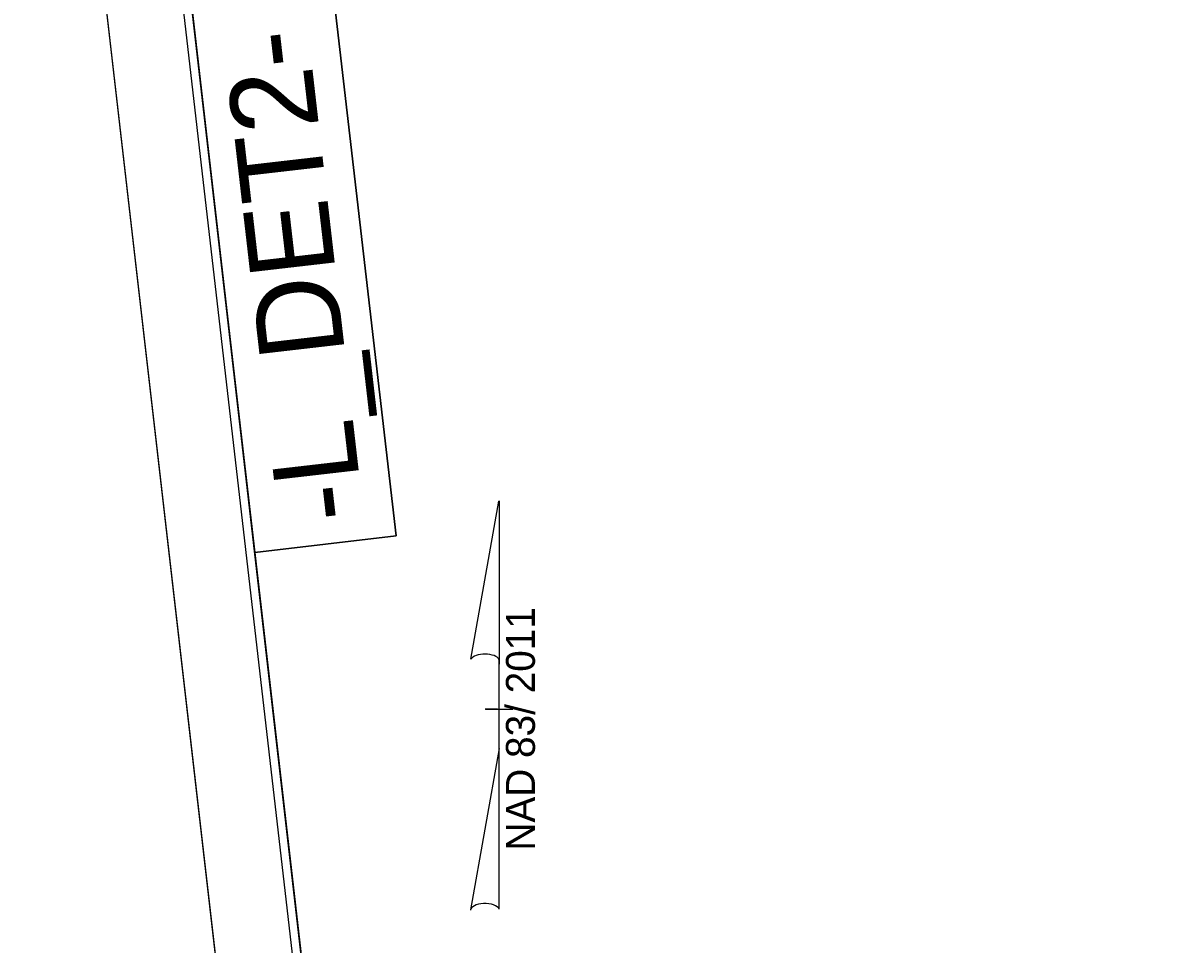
# Model space of a CAD drawing. Extents: x 477607 to 479438, y 495543 to 499482.
# Drawn here: x 477606.8 to 477940.1, y 496923.6 to 497193.8 of the extents above; entities that cross this region are included whole.
import ezdxf

# ---------------------------------------------------------------- set-up
doc = ezdxf.new("R2010")
doc.units = 0
for name, color, linetype in [('Old_Level_1', 7, 'Continuous'), ('Prop Grid Mask', 7, 'Continuous'), ('Prop North Arrow NAD83 for Plan Sheets CELL', 7, 'Continuous'), ('Sheet Border Standard 30in CELL', 7, 'Continuous'), ('Sheet Cutting Line CELL', 7, 'Continuous'), ('Sheet Layout Plan Border', 7, 'Continuous'), ('Sheet North Arrow Point CELL', 7, 'Continuous'), ('Sheet Plan CELL', 7, 'Continuous'), ('Sheet Plot Border Inside CELL', 7, 'Continuous'), ('Sheet Plot Border Outside CELL', 7, 'Continuous')]:
    doc.layers.add(name, color=color, linetype=linetype)

msp = doc.modelspace()

# ---------------------------------------------------------------- linework, layer by layer
at = {"layer": 'Prop Grid Mask'}
msp.add_lwpolyline([(477656.5, 497197.32), (477674.89, 497038.51), (477716.32, 497043.31), (477697.93, 497202.12)], close=True, dxfattribs=at)
at = {"layer": 'Prop North Arrow NAD83 for Plan Sheets CELL'}
for p, q in [((477738.24, 497007.22), (477746.44, 497053.57)), ((477746.49, 497053.57), (477746.44, 497053.57)), ((477746.49, 497053.57), (477746.44, 497053.57)), ((477746.49, 497053.57), (477746.49, 497005.77)), ((477746.49, 496980.97), (477746.49, 497007.17)), ((477746.49, 497005.77), (477746.49, 497007.12)), ((477742.49, 496992.57), (477742.44, 496992.57)), ((477746.04, 496992.57), (477742.49, 496992.57)), ((477742.54, 496992.57), (477750.54, 496992.57)), ((477746.49, 496980.97), (477738.14, 496933.72)), ((477746.54, 496933.92), (477746.49, 496980.97))]:
    msp.add_line(p, q, dxfattribs=at)
for centre, start_param, end_param in [((477742.37, 497006.72), 0.216388, 2.908219), ((477742.37, 496933.55), 0.201328, 3.141593)]:
    msp.add_ellipse(centre, major_axis=(4.23, -0.03), ratio=0.461098, start_param=start_param, end_param=end_param, dxfattribs=at)
at = {"layer": 'Sheet Border Standard 30in CELL'}
msp.add_lwpolyline([(477633.61, 497396.04), (477805.43, 495905.92), (478848.52, 496026.19), (478676.7, 497516.31)], close=True, dxfattribs=at)
at = {"layer": 'Sheet Cutting Line CELL'}
msp.add_line((477606.83, 497410.07), (477799.72, 495737.15), dxfattribs=at)
at = {"layer": 'Sheet Layout Plan Border'}
msp.add_lwpolyline([(478060.61, 495968.97), (478655.26, 496063.07), (478848.53, 496026.02), (478736, 497002.06), (478709.93, 496998.31), (478420.13, 496964.9), (478384.13, 497277.1), (478673.93, 497310.52), (478699.76, 497316.34), (478696.24, 497346.89), (478616.75, 497337.72), (478607.5, 497417.87), (478188.47, 497393.35), (477955.38, 497379.71), (477811.17, 497371.27), (477828.93, 497217.21), (477697.93, 497202.08), (477716.32, 497043.31), (477674.84, 497038.51), (477805.45, 495905.89)], close=True, dxfattribs=at)
msp.add_lwpolyline([(478060.61, 495968.97), (478655.26, 496063.07), (478848.53, 496026.02), (478736, 497002.06), (478709.93, 496998.31), (478420.13, 496964.9), (478384.13, 497277.1), (478673.93, 497310.52), (478699.76, 497316.34), (478696.24, 497346.89), (478616.75, 497337.72), (478607.5, 497417.87), (478188.47, 497393.35), (477955.38, 497379.71), (477811.17, 497371.27), (477828.93, 497217.21), (477697.93, 497202.08), (477716.32, 497043.31), (477674.84, 497038.51), (477805.45, 495905.89)], close=True, dxfattribs=at)
at = {"layer": 'Sheet North Arrow Point CELL'}
msp.add_line((477746.49, 497053.85), (477746.49, 497053.85), dxfattribs=at)
at = {"layer": 'Sheet Plan CELL'}
for points in [[(477633.61, 497396.08), (477805.43, 495905.92), (478848.52, 496026.19), (478676.7, 497516.33)], [(478848.52, 496026.19), (477805.45, 495905.89), (477656.51, 497197.32), (477805.59, 497214.52), (477782.68, 497413.24), (478676.7, 497516.33)]]:
    msp.add_lwpolyline(points, close=True, dxfattribs=at)
at = {"layer": 'Sheet Plot Border Inside CELL'}
msp.add_lwpolyline([(477629.65, 497408.17), (477820.53, 495752.64), (478868.69, 495873.49), (478677.8, 497529.02)], close=True, dxfattribs=at)
at = {"layer": 'Sheet Plot Border Outside CELL'}
msp.add_lwpolyline([(477606.83, 497410.07), (477799.72, 495737.15), (478892.48, 495863.15), (478699.59, 497536.07)], close=True, dxfattribs=at)

# ---------------------------------------------------------------- texts
at = {"layer": 'Old_Level_1'}
msp.add_text('-L_DET2-', height=25, rotation=96.5773, dxfattribs=at).set_placement((477706.92, 497048.82))
at = {"layer": 'Prop North Arrow NAD83 for Plan Sheets CELL'}
msp.add_text('NAD 83/ 2011', height=8.5, rotation=90, dxfattribs=at).set_placement((477757.01, 496951.05))

doc.saveas('drawing.dxf')
